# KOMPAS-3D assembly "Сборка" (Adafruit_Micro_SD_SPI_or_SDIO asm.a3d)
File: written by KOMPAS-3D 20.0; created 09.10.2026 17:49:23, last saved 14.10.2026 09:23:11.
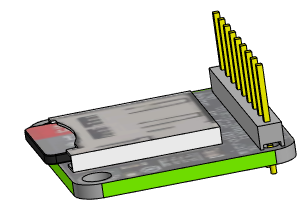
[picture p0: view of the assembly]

Document properties: Полное имя файла: D:\RicWork\Project-EPS32\box_compas\SD card\Adafruit_Micro_SD_SPI_or_SDIO asm.a3d

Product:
- Part/product: Сборка
    Масса: 0.00979968
  - Component [detail]: Деталь  | Масса: 0.00121292; source file: micro sd.m3d
  - Component [detail]: Деталь  | Масса: 0.0074136; source file: Adafruit_Micro_SD_SPI_or_SDIO.m3d
  - Component [detail]: Деталь  | Масса: 0.00117316; source file: ..\разъемы\pls_9.m3d

Referenced files in D:\RicWork\Project-EPS32\box_compas\SD card\: Adafruit_Micro_SD_SPI_or_SDIO.m3d, micro sd.m3d
Referenced files in D:\RicWork\Project-EPS32\box_compas\разъемы\: pls_9.m3d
